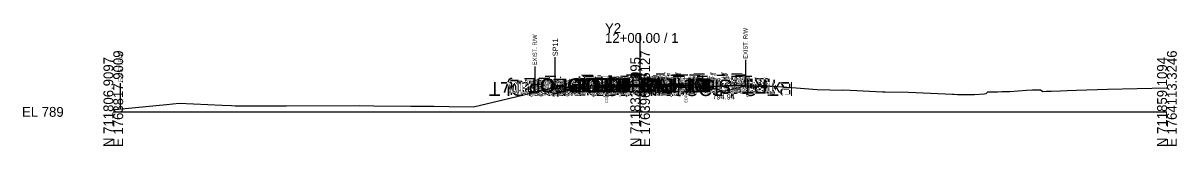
# Model space of a CAD drawing. Extents: x -26 to 1764011, y -10 to 712381.
# Drawn here: x -25.7 to 302.8, y 1990.3 to 2025.3 of the extents above; entities that cross this region are included whole.
import ezdxf

# ---------------------------------------------------------------- set-up
doc = ezdxf.new("R2010")
doc.units = 0
for name, color, linetype in [('Default', 7, 'Continuous'), ('Exist CMT Pavement', 7, 'Continuous'), ('Exist Cross Section Cell', 7, 'Continuous'), ('Exist XS Center Line Elevation Label', 7, 'Continuous'), ('Exist XS Ground Line', 7, 'Continuous'), ('Old_Level_10', 7, 'Continuous'), ('Prop CMT Pvmt Course 1', 7, 'Continuous'), ('Prop CMT Pvmt Course 3', 7, 'Continuous'), ('Prop CMT Pvmt Surface', 7, 'Continuous'), ('Prop CMT Pvmt Surface Shoulder', 7, 'Continuous'), ('Prop CMT Shld Paved Course 1', 7, 'Continuous'), ('Prop CMT Shld Paved Course 3', 7, 'Continuous'), ('Prop CMT Slope Grass', 7, 'Continuous'), ('Prop CMT Subgrade Earthwork', 7, 'Continuous'), ('Prop XS Ditch Standard Text', 7, 'Continuous'), ('Prop XS Earthwork Shape', 7, 'Continuous'), ('Prop XS SE Text', 7, 'Continuous'), ('Prop XS Shear Point Element', 7, 'Continuous'), ('Prop XS Side Slope Text', 7, 'Continuous'), ('Prop XS Wedging', 7, 'Continuous'), ('Scratch_Level_7', 7, 'Continuous')]:
    doc.layers.add(name, color=color, linetype=linetype)

msp = doc.modelspace()

# ---------------------------------------------------------------- linework, layer by layer
at = {"layer": 'Exist CMT Pavement'}
msp.add_lwpolyline([(140.49, 2007.1), (141.07, 2007.15), (141.68, 2007.19), (142.06, 2007.19), (143.03, 2007.2), (144.72, 2007.21), (145.57, 2007.21), (146.87, 2007.23), (148.11, 2007.24), (149.03, 2007.25), (150, 2007.25), (150.65, 2007.25), (151.19, 2007.24), (153.35, 2007.26), (154.26, 2007.25), (155.72, 2007.24), (156.04, 2007.23), (158.26, 2007.17), (159.82, 2007.11), (160.05, 2007.08)], dxfattribs=at)
at = {"layer": 'Exist Cross Section Cell'}
for p, q in [((150, 2000), (150, 2022.44)), ((0, 2000), (150, 2000)), ((150, 2000), (300, 2000))]:
    msp.add_line(p, q, dxfattribs=at)
at = {"layer": 'Exist XS Ground Line'}
msp.add_lwpolyline([(0, 2000.55), (0.48, 2000.67), (15.18, 2002.12), (18.74, 2002.48), (31.02, 2001.92), (33.62, 2001.8), (34.71, 2001.72), (35.04, 2001.72), (40.31, 2001.72), (42.59, 2001.72), (49.32, 2001.75), (70.12, 2001.78), (74.22, 2001.75), (84.71, 2001.61), (86.16, 2001.6), (89.7, 2001.6), (91.25, 2001.6), (95.66, 2001.56), (102.52, 2001.45), (120.85, 2005.76), (126.46, 2007.25), (128.46, 2007.12), (135.02, 2006.8), (137.1, 2006.88), (140.49, 2007.1), (141.07, 2007.15), (141.68, 2007.19), (142.06, 2007.19), (143.03, 2007.2), (144.72, 2007.21), (145.57, 2007.21), (146.87, 2007.23), (148.11, 2007.24), (149.03, 2007.25), (150, 2007.25), (150.65, 2007.25), (151.19, 2007.24), (153.35, 2007.26), (154.26, 2007.25), (155.72, 2007.24), (156.04, 2007.23), (158.26, 2007.17), (159.82, 2007.11), (160.8, 2007), (162.01, 2006.95), (163.07, 2007.03), (165.66, 2007.11), (166.89, 2007.11), (174.26, 2007.46), (174.73, 2007.48), (182.92, 2007.37), (187.87, 2007.3), (194.41, 2006.84), (200.43, 2006.35), (207.64, 2006.17), (207.97, 2006.26), (219.03, 2005.75), (219.75, 2005.66), (226.4, 2005.6), (238.9, 2005.05), (239.28, 2005.04), (240.35, 2004.99), (243.97, 2004.92), (245.18, 2004.93), (248, 2005.1), (248.57, 2005.19), (248.99, 2005.68), (250.13, 2005.7), (251.81, 2005.73), (253, 2005.76), (253.86, 2005.83), (255.31, 2005.84), (259.97, 2006.19), (261.7, 2006.29), (263.98, 2006.32), (264.64, 2005.83), (265.7, 2005.85), (267.02, 2005.87), (269.65, 2005.97), (271.61, 2006.12), (274.25, 2006.16), (283.08, 2006.42), (300, 2006.88)], dxfattribs=at)
at = {"layer": 'Old_Level_10'}
for p, q in [((180, 2014.81), (180, 2007.41)), ((120, 2012.96), (120, 2005.56)), ((1.98, 2008.22), (1.98, 2000.82)), ((140.49, 2007.1), (140.49, 2005.05)), ((163.07, 2007.03), (163.07, 2004.98))]:
    msp.add_line(p, q, dxfattribs=at)
at = {"layer": 'Prop CMT Pvmt Course 1'}
for points in [[(150, 2007.79), (138, 2007.48)], [(138, 2007.48), (138, 2007.23)], [(140.49, 2007.29), (150, 2007.54)], [(150, 2007.79), (162, 2008.1)], [(160.05, 2007.8), (150, 2007.54)], [(150, 2007.54), (150, 2007.79)], [(150, 2007.54), (150, 2007.54), (150, 2007.54)], [(162, 2007.85), (160.05, 2007.8)], [(160.05, 2007.8), (160.05, 2007.8)], [(162, 2008.1), (162, 2007.85)], [(138, 2007.23), (140.49, 2007.29)], [(140.49, 2007.29), (140.49, 2007.29)]]:
    msp.add_lwpolyline(points, dxfattribs=at)
at = {"layer": 'Prop CMT Pvmt Course 3'}
for points in [[(160.05, 2007.8), (162, 2007.85)], [(160.05, 2007.38), (160.05, 2007.8)], [(162, 2007.43), (160.05, 2007.38)], [(162, 2007.85), (162, 2007.43)], [(140.49, 2007.29), (138, 2007.23)], [(138, 2007.23), (138, 2006.81)], [(138, 2006.81), (140.49, 2006.88)], [(140.49, 2006.88), (140.49, 2007.29)]]:
    msp.add_lwpolyline(points, dxfattribs=at)
at = {"layer": 'Prop CMT Pvmt Surface'}
for p, q in [((138, 2007.48), (125.81, 2006.59)), ((125.81, 2006.59), (125.81, 2007.08))]:
    msp.add_line(p, q, dxfattribs=at)
for points in [[(150, 2007.79), (138, 2007.48)], [(150, 2007.79), (162, 2008.1)]]:
    msp.add_lwpolyline(points, dxfattribs=at)
at = {"layer": 'Prop CMT Pvmt Surface Shoulder'}
for points in [[(138, 2007.48), (138, 2007.48)], [(162, 2008.1), (162, 2008.1)]]:
    msp.add_lwpolyline(points, dxfattribs=at)
at = {"layer": 'Prop CMT Shld Paved Course 1'}
for points in [[(138, 2007.48), (137.74, 2007.22)], [(138, 2007.48), (138, 2007.48)], [(138, 2007.23), (138, 2007.48)], [(162, 2008.1), (162, 2008.1)], [(162, 2008.1), (162.26, 2007.84)], [(162, 2007.85), (162, 2008.1)], [(162.26, 2007.84), (162, 2007.85)], [(137.74, 2007.22), (138, 2007.23)]]:
    msp.add_lwpolyline(points, dxfattribs=at)
at = {"layer": 'Prop CMT Shld Paved Course 3'}
for points in [[(162, 2007.85), (162.26, 2007.84)], [(162, 2007.51), (162, 2007.85)], [(162.68, 2007.42), (162, 2007.43)], [(162.26, 2007.84), (162.68, 2007.42)], [(137.74, 2007.22), (137.32, 2006.8)], [(137.32, 2006.8), (138, 2006.81)], [(138, 2007.23), (137.74, 2007.22)], [(138, 2006.9), (138, 2007.23)]]:
    msp.add_lwpolyline(points, dxfattribs=at)
at = {"layer": 'Prop CMT Slope Grass'}
msp.add_lwpolyline([(162, 2008.1), (166, 2007.94), (174, 2005.94), (179.9, 2007.41)], dxfattribs=at)
at = {"layer": 'Prop CMT Subgrade Earthwork'}
for p, q in [((160.05, 2007.38), (162, 2007.43)), ((160.05, 2007.38), (160.05, 2007.08)), ((162, 2007.43), (162.68, 2007.42)), ((134.87, 2006.75), (125.81, 2006.09)), ((125.81, 2006.09), (125.81, 2006.59)), ((134.87, 2006.75), (138, 2006.81)), ((140.49, 2006.88), (138, 2006.81)), ((140.49, 2007.1), (140.49, 2006.88))]:
    msp.add_line(p, q, dxfattribs=at)
msp.add_lwpolyline([(163.31, 2008.04), (162.68, 2007.42)], dxfattribs=at)
at = {"layer": 'Prop XS Earthwork Shape'}
for points in [[(134, 2007.16), (132.97, 2006.9), (135.02, 2006.8), (137.1, 2006.88), (137.23, 2006.88), (136.74, 2007.38)], [(166, 2007.94), (168.92, 2007.21), (166.89, 2007.11), (165.66, 2007.11), (163.07, 2007.03), (162.01, 2006.95), (160.8, 2007), (160.05, 2007.08), (160.05, 2007.38), (162, 2007.43), (162.68, 2007.42), (163.31, 2008.04)], [(174, 2005.94), (179.9, 2007.41), (174.73, 2007.48), (174.26, 2007.46), (168.92, 2007.21)], [(126, 2005.16), (122.19, 2006.11), (126.46, 2007.25), (128.46, 2007.12), (132.97, 2006.9)], [(140.49, 2007.1), (140.49, 2006.88), (138, 2006.81), (137.32, 2006.8), (137.23, 2006.88)]]:
    msp.add_lwpolyline(points, close=True, dxfattribs=at)
at = {"layer": 'Prop XS Shear Point Element'}
msp.add_line((125.81, 2006.59), (125.81, 2015.54), dxfattribs=at)
at = {"layer": 'Prop XS Wedging'}
for p, q in [((148.33, 2007.49), (140.49, 2007.29)), ((148.39, 2007.56), (148.08, 2007.24)), ((148.08, 2007.24), (148.33, 2007.49)), ((148.33, 2007.49), (148.08, 2007.24)), ((150, 2007.54), (148.33, 2007.49)), ((160.05, 2007.8), (150, 2007.54)), ((160.05, 2007.38), (160.05, 2007.8)), ((160.05, 2007.08), (160.05, 2007.38)), ((140.49, 2007.29), (140.49, 2007.1)), ((140.49, 2007.04), (148.08, 2007.24)), ((140.49, 2007.1), (141.07, 2007.15)), ((143.03, 2007.2), (144.72, 2007.21)), ((146.87, 2007.23), (148.08, 2007.24)), ((149.03, 2007.25), (150, 2007.25)), ((151.19, 2007.24), (153.35, 2007.26))]:
    msp.add_line(p, q, dxfattribs=at)
for points in [[(141.07, 2007.15), (141.68, 2007.19), (142.06, 2007.19), (143.03, 2007.2)], [(144.72, 2007.21), (145.57, 2007.21), (146.87, 2007.23)], [(148.08, 2007.24), (148.11, 2007.24), (149.03, 2007.25)], [(150, 2007.25), (150.65, 2007.25), (151.19, 2007.24)], [(153.35, 2007.26), (154.26, 2007.25), (155.72, 2007.24), (156.04, 2007.23), (158.26, 2007.17)], [(158.26, 2007.17), (159.82, 2007.11), (160.05, 2007.08)]]:
    msp.add_lwpolyline(points, dxfattribs=at)

# ---------------------------------------------------------------- texts
at = {"layer": 'Default'}
msp.add_text('-', height=0.0001, dxfattribs=at).set_placement((0, 2000))
at = {"layer": 'Exist Cross Section Cell'}
for s, p in [('Y2', (140, 2022.44)), ('12+00.00 / 1', (140, 2019.64)), ('EL 789', (-26, 1998.6))]:
    msp.add_text(s, height=2.8, dxfattribs=at).set_placement(p)
for s, p in [('E 1763817.9009', (2.8, 1990)), ('E 1763965.6127', (152.8, 1990)), ('E 1764113.3246', (302.8, 1990)), ('N 711806.9097', (0, 1990)), ('N 711833.0095', (150, 1990)), ('N 711859.1094', (300, 1990))]:
    msp.add_text(s, height=2.8, rotation=90, dxfattribs=at).set_placement(p)
at = {"layer": 'Exist XS Center Line Elevation Label'}
msp.add_text('796.25', height=1, dxfattribs=at).set_placement((147.87, 2005.25))
at = {"layer": 'Old_Level_10'}
for s, height, p in [('EXIST. R/W', 1.181, (120.59, 2013.26)), ('EXIST. R/W', 1.181, (180.59, 2015.11)), ('EXIST. R/W', 1.181, (2.57, 2008.52)), ('EOP', 0.787, (140.88, 2002.65)), ('EOP', 0.787, (163.46, 2002.58))]:
    msp.add_text(s, height=height, rotation=90, dxfattribs=at).set_placement(p)
at = {"layer": 'Prop XS Ditch Standard Text'}
msp.add_text('794.94', height=1.5, dxfattribs=at).set_placement((170.61, 2003.53))
at = {"layer": 'Prop XS SE Text'}
for s, rotation, p in [('0.073', 5.7123, (129.75, 2007.23)), ('0.026', 1.473, (141.36, 2008.57)), ('0.026', 1.473, (153.36, 2008.87))]:
    msp.add_text(s, height=1.5, rotation=rotation, dxfattribs=at).set_placement(p)
at = {"layer": 'Prop XS Shear Point Element'}
msp.add_text('SP11', height=1.5, rotation=90, dxfattribs=at).set_placement((126.59, 2015.83))
at = {"layer": 'Prop XS Side Slope Text'}
for rotation, p in [(345.9638, (166.22, 2008.5)), (14.0362, (176.79, 2007.25))]:
    msp.add_text('4:1', height=1.5, rotation=rotation, dxfattribs=at).set_placement(p)
at = {"layer": 'Scratch_Level_7'}
for s, p in [('LT_PV1_OEOT', (155.63, 2009.48)), ('LT_PS1_OEOP', (155.9, 2009.48)), ('RT_PV1_IEEOP', (169.32, 2009.54)), ('LT_PV1_IEEOP', (168.82, 2009.54)), ('RT_PV2_IEEOP', (170.33, 2009.54)), ('LT_PV2_IEEOP', (169.82, 2009.54)), ('PV1_PGL', (160.68, 2009.79)), ('PV2_PGL', (161.68, 2009.54)), ('RT_PV1_OEEOP', (180.25, 2009.8)), ('RT_PV2_OEEOP', (181.26, 2009.8)), ('RT_PS3_Shelf_Out', (187.28, 2009.5)), ('RT_PV1_OEOT', (180.14, 2010.1)), ('RT_PS1_OEOP', (180.41, 2010.1)), ('RT_PV2_OEOT', (181.15, 2009.85)), ('RT_PV3_OEOT', (181.18, 2009.51)), ('RT_PS2_OEOP', (181.67, 2009.84)), ('RT_PS3_OEOP', (182.04, 2009.5)), ('RT_GS_OS_CTL', (186.12, 2009.78)), ('LT_Sub_OSS_DLT', (153.06, 2008.51)), ('Exterior Boundary', (153.88, 2008.51)), ('LT_Sub_Trench_Out', (162.51, 2008.54)), ('LT_GS_OS_CTL', (153.62, 2009.16)), ('LT_PS3_Shelf_Out', (161.59, 2008.88)), ('LT_Slope_Fill', (150.24, 2008.9)), ('LT_PS3_OEOP', (156.35, 2008.88)), ('LT_PV1_OEEOP', (160.18, 2009.29)), ('LT_PS2_OEOP', (156.66, 2009.22)), ('LT_PV2_OEOT', (156.64, 2009.23)), ('LT_PV3_OEOT', (156.67, 2008.9)), ('LT_Sub_OEOT', (156.11, 2008.56)), ('LT_PV2_OEEOP', (161.19, 2009.29)), ('LT_PV3_OEEOP', (161.22, 2008.96)), ('LT_Sub_OEEOP', (160.66, 2008.63)), ('RT_Sub_Trench_Out', (188.88, 2009.16)), ('RT_PV3_OEEOP', (181.29, 2009.46)), ('RT_Sub_OEEOP', (180.72, 2009.13)), ('RT_Sub_OEOT', (180.61, 2009.18)), ('RT_Sub_OSS_DLT', (193.35, 2008.51)), ('Exterior Boundary', (193.67, 2008.51)), ('RT_Slope_Fill', (186.15, 2009.18))]:
    msp.add_text(s, height=4, rotation=180, dxfattribs=at).set_placement(p)

doc.saveas('drawing.dxf')
